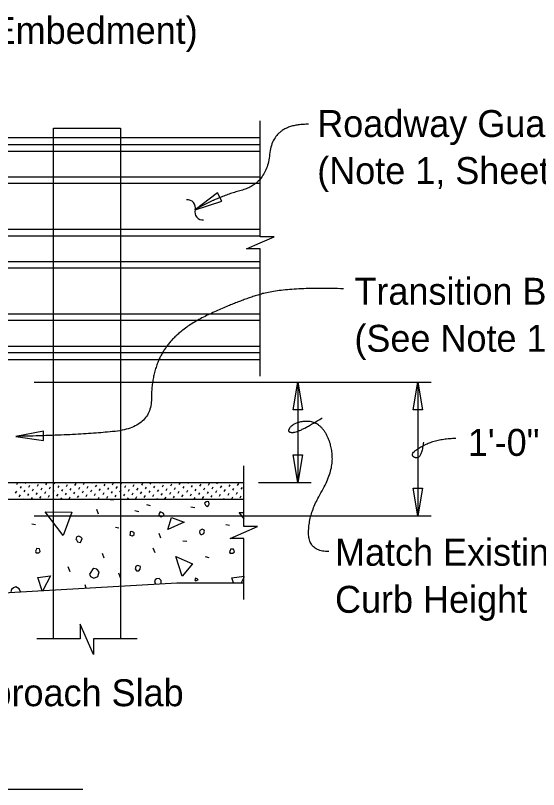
# Model space of a CAD drawing. Extents: x 0 to 41.1, y 0 to 26.
# Drawn here: x 9.77 to 13.68, y 8.65 to 14.44 of the extents above; entities that cross this region are included whole.
import ezdxf

# ---------------------------------------------------------------- set-up
doc = ezdxf.new("R2010")
doc.units = 0
for name, color, linetype in [('Dimension', 7, 'Continuous'), ('Miscellaneous', 7, 'Continuous'), ('TextStructures', 7, 'Continuous'), ('TrafBarrierConc', 7, 'Continuous')]:
    doc.layers.add(name, color=color, linetype=linetype)

# ---------------------------------------------------------------- blocks, each defined once
blk = doc.blocks.new('Terminator-Arrow')
at = {"layer": 'Dimension'}
blk.add_lwpolyline([(0, 0), (-0.00041, 0.000069), (-0.00041, -0.000069)], close=True, dxfattribs=at)

msp = doc.modelspace()

# ---------------------------------------------------------------- linework, layer by layer
at = {"layer": 'Dimension'}
for p, q in [((9.9066, 11.6946), (12.8809, 11.6946)), ((11.882, 11.6948), (11.882, 10.9446)), ((12.7812, 11.6948), (12.7812, 10.6948)), ((11.587, 10.9446), (11.9817, 10.9446)), ((9.9066, 10.6946), (12.8809, 10.6946)), ((10.272, 8.6469), (6.3751, 8.6469))]:
    msp.add_line(p, q, dxfattribs=at)
for points in [[(11.6001, 11.7396), (11.6001, 12.693), (11.4968, 12.693), (11.6001, 12.738), (11.7034, 12.783), (11.6001, 12.783), (11.6001, 13.6497)], [(11.4776, 10.0696), (11.4776, 10.5246), (11.3743, 10.5246), (11.4776, 10.5696), (11.5809, 10.6146), (11.4776, 10.6146), (11.4776, 11.0697)], [(10.6776, 9.7744), (10.3523, 9.7744), (10.3523, 9.6582), (10.2529, 9.8832), (10.2529, 9.7744), (9.9276, 9.7744)]]:
    msp.add_lwpolyline(points, dxfattribs=at)
for points in [[(11.1123, 12.9847), (11.3135, 13.0487), (11.2812, 13.1115)], [(9.7689, 11.2895), (9.9777, 11.2577), (9.9766, 11.3283)]]:
    msp.add_lwpolyline(points, close=True, dxfattribs=at)
for centre, start, end in [((11.0552, 13.0002), 344.25937, 95.98659), ((11.17, 12.9679), 164.25937, 275.98659)]:
    msp.add_arc(centre, 0.0596, start, end, dxfattribs=at)
for points in [[(11.9622, 13.6245), (11.6944, 13.6281), (11.6483, 13.1814), (11.2819, 13.083), (11.1122, 12.9847)], [(12.2244, 12.3939), (11.7789, 12.4076), (11.4019, 12.291), (10.9813, 12.0877), (10.7857, 11.7904), (10.7857, 11.3565), (10.2382, 11.2973), (9.7689, 11.2895)], [(12.1128, 10.4271), (11.962, 10.4271), (11.962, 10.7084), (12.1402, 11.0102), (12.1402, 11.2297), (12.0374, 11.4012), (11.866, 11.4012), (11.7906, 11.3189), (11.8935, 11.3189), (12.0648, 11.4286)], [(12.8227, 11.2472), (12.8067, 11.1058), (12.7053, 11.1578), (12.9227, 11.2752), (13.064, 11.2752)]]:
    msp.add_open_spline(points, degree=2, dxfattribs=at)
at = {"layer": 'Miscellaneous'}
for p, q in [((5.7567, 13.5247), (11.6026, 13.5247)), ((5.7567, 13.4725), (11.6026, 13.4725)), ((5.7567, 13.4242), (11.6026, 13.4242)), ((5.7567, 13.2314), (11.6026, 13.2314)), ((5.7567, 13.1832), (11.6026, 13.1832)), ((5.7567, 12.8392), (11.6026, 12.8392)), ((5.7567, 12.791), (11.6026, 12.791)), ((5.7567, 12.5982), (11.6026, 12.5982)), ((5.7567, 12.5501), (11.6026, 12.5501)), ((5.7567, 12.2061), (11.6026, 12.2061)), ((5.7567, 12.1579), (11.6026, 12.1579)), ((5.7567, 11.9651), (11.6026, 11.9651)), ((5.7567, 11.9168), (11.6026, 11.9168)), ((5.7567, 11.8646), (11.6026, 11.8646)), ((9.7764, 10.9291), (9.7845, 10.9431)), ((9.8041, 10.9014), (9.8122, 10.9154)), ((9.8399, 10.9372), (9.8442, 10.9447)), ((9.8676, 10.9095), (9.8757, 10.9235)), ((9.8953, 10.8818), (9.9034, 10.8958)), ((9.9311, 10.9176), (9.9392, 10.9316)), ((9.9588, 10.8899), (9.9669, 10.9039)), ((9.9946, 10.9257), (10.0027, 10.9397)), ((10.0223, 10.898), (10.0304, 10.912)), ((10.0581, 10.9338), (10.0644, 10.9447)), ((10.0858, 10.9061), (10.0939, 10.9201)), ((10.1135, 10.8784), (10.1216, 10.8924)), ((10.1216, 10.9419), (10.1232, 10.9447)), ((10.1493, 10.9142), (10.1574, 10.9282)), ((10.177, 10.8865), (10.1851, 10.9005)), ((10.2128, 10.9223), (10.2209, 10.9363)), ((10.2405, 10.8946), (10.2486, 10.9086)), ((10.2763, 10.9304), (10.2844, 10.9444)), ((10.304, 10.9027), (10.3121, 10.9167)), ((10.3317, 10.875), (10.3398, 10.889)), ((10.3398, 10.9385), (10.3433, 10.9447)), ((10.3675, 10.9108), (10.3756, 10.9248)), ((10.3952, 10.8831), (10.4033, 10.8971)), ((10.4309, 10.9189), (10.4391, 10.9329)), ((10.4586, 10.8912), (10.4667, 10.9052)), ((10.4944, 10.927), (10.5025, 10.941)), ((10.5221, 10.8993), (10.5302, 10.9133)), ((10.5579, 10.9351), (10.5634, 10.9447)), ((10.5856, 10.9074), (10.5937, 10.9214)), ((10.6133, 10.8797), (10.6214, 10.8937)), ((10.6214, 10.9432), (10.6223, 10.9447)), ((10.6491, 10.9155), (10.6572, 10.9295)), ((10.6768, 10.8878), (10.6849, 10.9018)), ((10.7126, 10.9236), (10.7207, 10.9376)), ((10.7403, 10.8959), (10.7484, 10.9099)), ((10.7761, 10.9317), (10.7836, 10.9447)), ((10.8038, 10.904), (10.8119, 10.918)), ((10.8315, 10.8763), (10.8396, 10.8903)), ((10.8396, 10.9398), (10.8424, 10.9447)), ((10.8673, 10.9121), (10.8754, 10.9261)), ((10.895, 10.8844), (10.9031, 10.8984)), ((10.9308, 10.9202), (10.9389, 10.9342)), ((10.9585, 10.8925), (10.9666, 10.9065)), ((10.9943, 10.9283), (11.0024, 10.9423)), ((11.022, 10.9007), (11.0301, 10.9146)), ((11.0578, 10.9364), (11.0625, 10.9447)), ((11.0855, 10.9088), (11.0936, 10.9227)), ((11.1132, 10.8811), (11.1213, 10.8951)), ((11.1213, 10.9446), (11.1213, 10.9447)), ((11.149, 10.9169), (11.1571, 10.9309)), ((11.1767, 10.8892), (11.1848, 10.9032)), ((11.2124, 10.925), (11.2206, 10.939)), ((11.2401, 10.8973), (11.2482, 10.9113)), ((11.2759, 10.9331), (11.2827, 10.9447)), ((11.3036, 10.9054), (11.3117, 10.9194)), ((11.3313, 10.8777), (11.3394, 10.8917)), ((11.3394, 10.9412), (11.3415, 10.9447)), ((11.3671, 10.9135), (11.3752, 10.9275)), ((11.3948, 10.8858), (11.4029, 10.8998)), ((11.4306, 10.9216), (11.4387, 10.9356)), ((11.4583, 10.8939), (11.4664, 10.9079)), ((9.7683, 10.8656), (9.7764, 10.8796)), ((9.796, 10.8379), (9.8041, 10.8519)), ((9.8318, 10.8737), (9.8399, 10.8877)), ((9.8595, 10.846), (9.8676, 10.86)), ((9.888, 10.8197), (9.8953, 10.8323)), ((9.923, 10.8541), (9.9311, 10.8681)), ((9.9507, 10.8264), (9.9588, 10.8404)), ((9.9865, 10.8622), (9.9946, 10.8762)), ((10.0142, 10.8345), (10.0223, 10.8485)), ((10.05, 10.8703), (10.0581, 10.8843)), ((10.0777, 10.8426), (10.0858, 10.8566)), ((10.1412, 10.8507), (10.1493, 10.8647)), ((10.1689, 10.823), (10.177, 10.837)), ((10.2047, 10.8588), (10.2128, 10.8728)), ((10.2324, 10.8311), (10.2405, 10.8451)), ((10.2682, 10.8669), (10.2763, 10.8809)), ((10.2959, 10.8392), (10.304, 10.8532)), ((10.3594, 10.8473), (10.3675, 10.8613)), ((10.3871, 10.8197), (10.3952, 10.8336)), ((10.4228, 10.8554), (10.4309, 10.8694)), ((10.4505, 10.8277), (10.4586, 10.8417)), ((10.4863, 10.8635), (10.4944, 10.8775)), ((10.514, 10.8358), (10.5221, 10.8498)), ((10.5498, 10.8716), (10.5579, 10.8856)), ((10.5775, 10.8439), (10.5856, 10.8579)), ((10.641, 10.852), (10.6491, 10.866)), ((10.6687, 10.8243), (10.6768, 10.8383)), ((10.7045, 10.8601), (10.7126, 10.8741)), ((10.7322, 10.8324), (10.7403, 10.8464)), ((10.768, 10.8682), (10.7761, 10.8822)), ((10.7957, 10.8405), (10.8038, 10.8545)), ((10.8592, 10.8486), (10.8673, 10.8626)), ((10.8869, 10.821), (10.895, 10.8349)), ((10.9227, 10.8568), (10.9308, 10.8707)), ((10.9504, 10.8291), (10.9585, 10.8431)), ((10.9862, 10.8649), (10.9943, 10.8788)), ((11.0139, 10.8372), (11.022, 10.8512)), ((11.0497, 10.873), (11.0578, 10.887)), ((11.0774, 10.8453), (11.0855, 10.8593)), ((11.1063, 10.8197), (11.1132, 10.8316)), ((11.1409, 10.8534), (11.149, 10.8674)), ((11.1685, 10.8257), (11.1767, 10.8397)), ((11.2043, 10.8615), (11.2124, 10.8755)), ((11.232, 10.8338), (11.2401, 10.8478)), ((11.2678, 10.8696), (11.2759, 10.8836)), ((11.2955, 10.8419), (11.3036, 10.8559)), ((11.359, 10.85), (11.3671, 10.864)), ((11.3867, 10.8223), (11.3948, 10.8363)), ((11.4225, 10.8581), (11.4306, 10.8721)), ((11.4502, 10.8304), (11.4583, 10.8444)), ((9.8292, 10.8197), (9.8318, 10.8242)), ((10.0493, 10.8197), (10.05, 10.8208)), ((10.1081, 10.8197), (10.1135, 10.8289)), ((10.3283, 10.8197), (10.3317, 10.8255)), ((10.5484, 10.8197), (10.5498, 10.8221)), ((10.6072, 10.8197), (10.6133, 10.8302)), ((10.7488, 10.779), (10.7771, 10.7719)), ((10.8273, 10.8197), (10.8315, 10.8268)), ((11.0475, 10.8197), (11.0497, 10.8235)), ((11.2676, 10.8197), (11.2678, 10.8201)), ((11.3264, 10.8197), (11.3313, 10.8282)), ((10.3882, 10.7082), (10.3758, 10.7418)), ((10.6622, 10.7348), (10.6905, 10.7277)), ((11.0794, 10.763), (11.1094, 10.7577)), ((9.8897, 10.634), (9.9162, 10.6287)), ((10.5154, 10.6092), (10.542, 10.6039)), ((11.3428, 10.6305), (11.3693, 10.6252)), ((10.8549, 10.5279), (10.8425, 10.5615)), ((11.0193, 10.5085), (11.0511, 10.5049)), ((10.8124, 10.4183), (10.7983, 10.4537)), ((10.4324, 10.3777), (10.4182, 10.413)), ((11.1872, 10.39), (11.2155, 10.383)), ((10.176, 10.2769), (10.1619, 10.3123)), ((10.5543, 10.2309), (10.5402, 10.2663)), ((10.2978, 10.1544), (10.2892, 10.1779))]:
    msp.add_line(p, q, dxfattribs=at)
for points in [[(10.0525, 9.7744), (10.0525, 13.5946), (10.5525, 13.5946), (10.5525, 9.7744)], [(10.4768, 10.8197), (10.4801, 10.8143), (10.5031, 10.8161), (10.5066, 10.8197)], [(11.1907, 10.7754), (11.2013, 10.7648), (11.2119, 10.7719), (11.219, 10.7825), (11.2155, 10.8002), (11.2066, 10.8019), (11.1943, 10.8002), (11.1837, 10.7896), (11.1907, 10.7754)], [(10.1248, 10.5474), (9.9904, 10.7242), (10.1902, 10.7224), (10.1248, 10.5474)], [(10.8513, 10.6906), (10.8637, 10.6888), (10.8761, 10.6941), (10.8796, 10.7047), (10.8743, 10.7135), (10.8637, 10.7206), (10.8513, 10.7259), (10.8442, 10.7118), (10.8407, 10.7012), (10.8513, 10.6906)], [(11.4801, 10.6725), (11.4435, 10.7206), (11.4801, 10.7203)], [(10.9079, 10.5916), (10.9362, 10.6835), (11.0299, 10.6464), (10.9079, 10.5916)], [(10.2238, 10.5156), (10.2326, 10.4996), (10.2538, 10.4961), (10.2627, 10.512), (10.2662, 10.5262), (10.2573, 10.535), (10.2414, 10.5438), (10.2255, 10.5385), (10.2202, 10.5226), (10.2238, 10.5156)], [(10.6233, 10.5509), (10.6427, 10.5456), (10.6551, 10.5544), (10.6569, 10.5668), (10.6533, 10.5704), (10.6392, 10.5774), (10.6268, 10.5757), (10.625, 10.5633), (10.6233, 10.5509)], [(11.1554, 10.5562), (11.1624, 10.5562), (11.1766, 10.5633), (11.1819, 10.5792), (11.1801, 10.588), (11.166, 10.5951), (11.1483, 10.5845), (11.1448, 10.5739), (11.1483, 10.5633), (11.1554, 10.5562)], [(9.9215, 10.4183), (9.9427, 10.4183), (9.9533, 10.4289), (9.948, 10.4484), (9.925, 10.4501), (9.9215, 10.4395), (9.9162, 10.4307), (9.9215, 10.4183), (9.9179, 10.4219)], [(11.3746, 10.4148), (11.3958, 10.4148), (11.4064, 10.4254), (11.4011, 10.4448), (11.3781, 10.4466), (11.3746, 10.436), (11.3693, 10.4272), (11.3746, 10.4148), (11.371, 10.4183)], [(11.0157, 10.2433), (10.968, 10.39), (11.0935, 10.3352), (11.0157, 10.2433)], [(10.6639, 10.2981), (10.6728, 10.2822), (10.6922, 10.284), (10.7011, 10.2964), (10.7028, 10.3158), (10.6905, 10.3211), (10.6816, 10.3229), (10.671, 10.3193), (10.6675, 10.3158), (10.6639, 10.2981)], [(10.3298, 10.2398), (10.3528, 10.2274), (10.3829, 10.2398), (10.3952, 10.2769), (10.3776, 10.2946), (10.3546, 10.2999), (10.344, 10.2928), (10.3316, 10.2734), (10.3228, 10.2575), (10.3298, 10.2398)], [(9.9677, 10.1348), (9.9356, 10.2345), (10.0293, 10.2469), (9.9717, 10.1351)], [(10.8578, 10.1876), (10.8584, 10.1885), (10.8584, 10.2097), (10.8425, 10.2256), (10.823, 10.2239), (10.8142, 10.215), (10.8089, 10.1991)], [(10.8089, 10.1991), (10.8159, 10.1851)], [(11.1147, 10.208), (11.1342, 10.2168), (11.1271, 10.2239), (11.1147, 10.2292), (11.1094, 10.2168), (11.1147, 10.208)], [(11.4004, 10.1946), (11.3887, 10.2309), (11.4801, 10.243)], [(11.4801, 10.2388), (11.4573, 10.1946)], [(9.8043, 10.1252), (9.7942, 10.1496), (9.7694, 10.1638), (9.7518, 10.1567), (9.7376, 10.1426), (9.7323, 10.1266)]]:
    msp.add_lwpolyline(points, dxfattribs=at)
at = {"layer": 'TrafBarrierConc'}
for p, q in [((5.7566, 10.9447), (11.4801, 10.9447)), ((7.7567, 10.8197), (11.4801, 10.8197)), ((6.7566, 9.9446), (10.9766, 10.1946)), ((10.9766, 10.1946), (11.4801, 10.1946))]:
    msp.add_line(p, q, dxfattribs=at)

# ---------------------------------------------------------------- block references
at = {"layer": 'Dimension', "xscale": 506.349, "yscale": -512.1577380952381}
for p, rotation in [((11.8813, 11.6944), 90), ((12.7805, 11.6944), 90), ((11.8816, 10.9443), -90), ((12.7805, 10.6943), -90)]:
    msp.add_blockref('Terminator-Arrow', p, dxfattribs=dict(at, rotation=rotation))

# ---------------------------------------------------------------- texts
at = {"layer": 'Dimension'}
for s, p in [('Dowel Bars 4L (10" Embedment) ', (7.2006, 14.2264)), ('Roadway Guardrail Transition ', (12.0271, 13.5293)), ('(Note 1, Sheet 1)', (12.0271, 13.1773)), ('Transition Block', (12.3056, 12.2743)), ('(See Note 1)', (12.3056, 11.9223)), ('Match Existing ', (12.1603, 10.3212)), ('Curb Height', (12.1603, 9.9692))]:
    msp.add_text(s, height=0.2016, dxfattribs=at).set_placement(p)
at = {"layer": 'TextStructures'}
for s, p in [('1\'-0"', (13.1546, 11.1434)), ('Existing Approach Slab', (8.2391, 9.2703))]:
    msp.add_text(s, height=0.2016, dxfattribs=at).set_placement(p)

doc.saveas('drawing.dxf')
